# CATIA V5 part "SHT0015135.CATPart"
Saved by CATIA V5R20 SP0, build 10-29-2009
Part number: Part29
Bounding box of the stored display mesh (mm): x 111.5 to 139.496, y -20.2 to 20.2, z 13.7 to 62.58
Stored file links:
  E:\张磊\转盘自研\外发冻结数据图纸\2D\2022.11.18-单件图纸\SHT0015135-气动转盘解锁钣金\SHT0015135.CATPart
  SHT0015135.CATPart
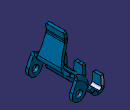
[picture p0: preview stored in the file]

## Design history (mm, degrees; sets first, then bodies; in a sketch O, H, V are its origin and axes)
Body1 (main body)
Body2 "锁止片"
  Solid1: solid without history
Body3 "锁止片   改齿口尺寸，干涉导致啮合不到位230427"
  Solid2: solid without history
